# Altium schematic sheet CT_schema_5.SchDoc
size 293 x 258 mm
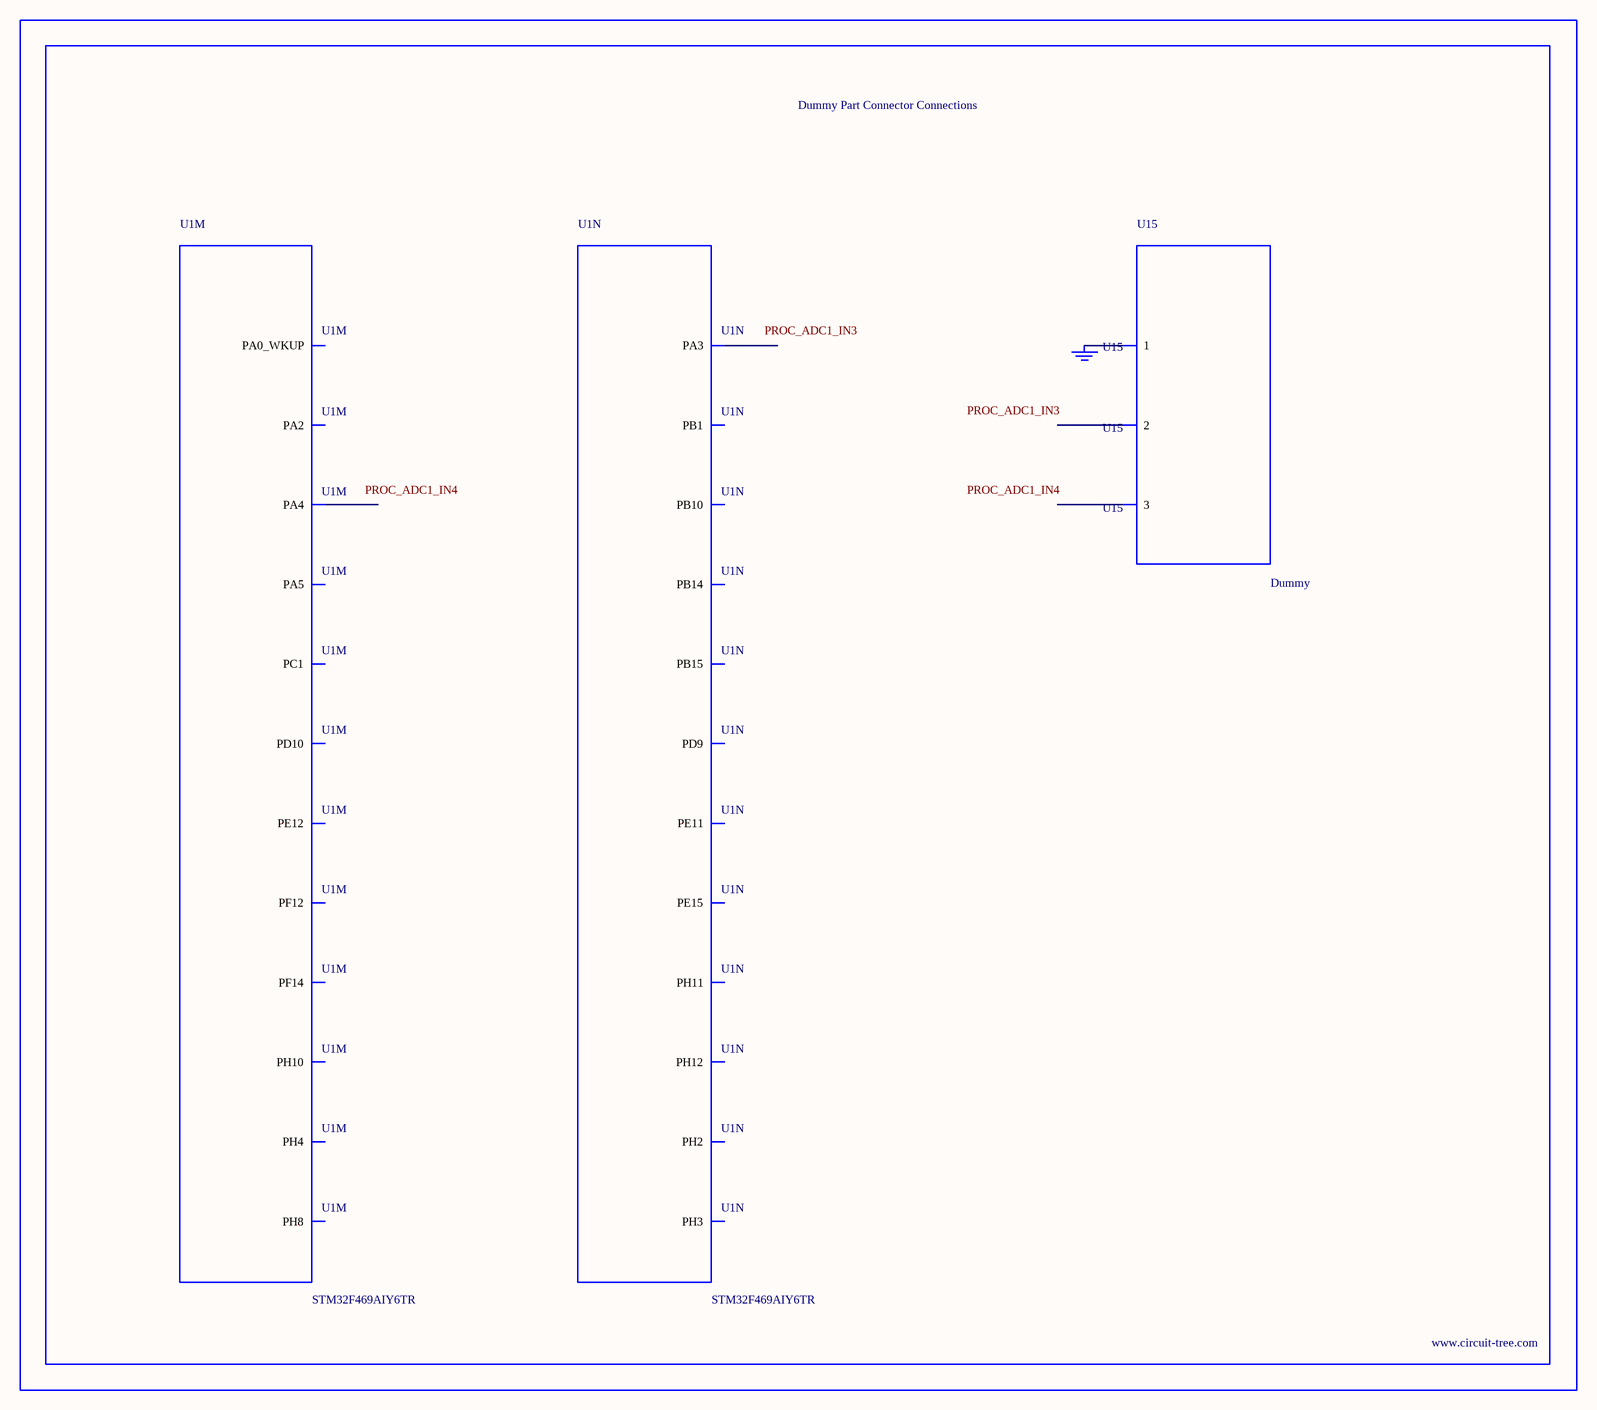
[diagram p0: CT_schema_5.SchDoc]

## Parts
BORDER4  (no value)
GND_INSTANCE_4_0  (no value)
U1  STM32F469AIY6TR  [WLCSP168]  (parts M,N of 14)
U15  Dummy  [DUMMY_PACKAGE_165]

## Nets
NetGND_INSTANCE_4_0_0: GND_INSTANCE_4_0.0(GND) U15.1

Not connected (* = marked no-connect by the designer): U1 L7(PF14) L8(PA5) L9(PA2) L10(PA0_WKUP) L12(PC1) M3(PD10) M4(PH10) M5(PH8) M6(PE12) M8(PF12) M9(PA4) M10(PH4) M11(PH2) N1(PD9) N2(PB15) N3(PH11) N5(PB10) N6(PE11) N9(PB1) N10(PA3) N12(PH3) P1(PB14) P2(PH12) P5(PE15); U15 2 3

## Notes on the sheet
- Labels drawn without touching a wire or pin: PROC_ADC1_IN3, PROC_ADC1_IN4

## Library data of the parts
BORDER4 = BORDER_PAGE4
GND_INSTANCE_4_0 = GND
